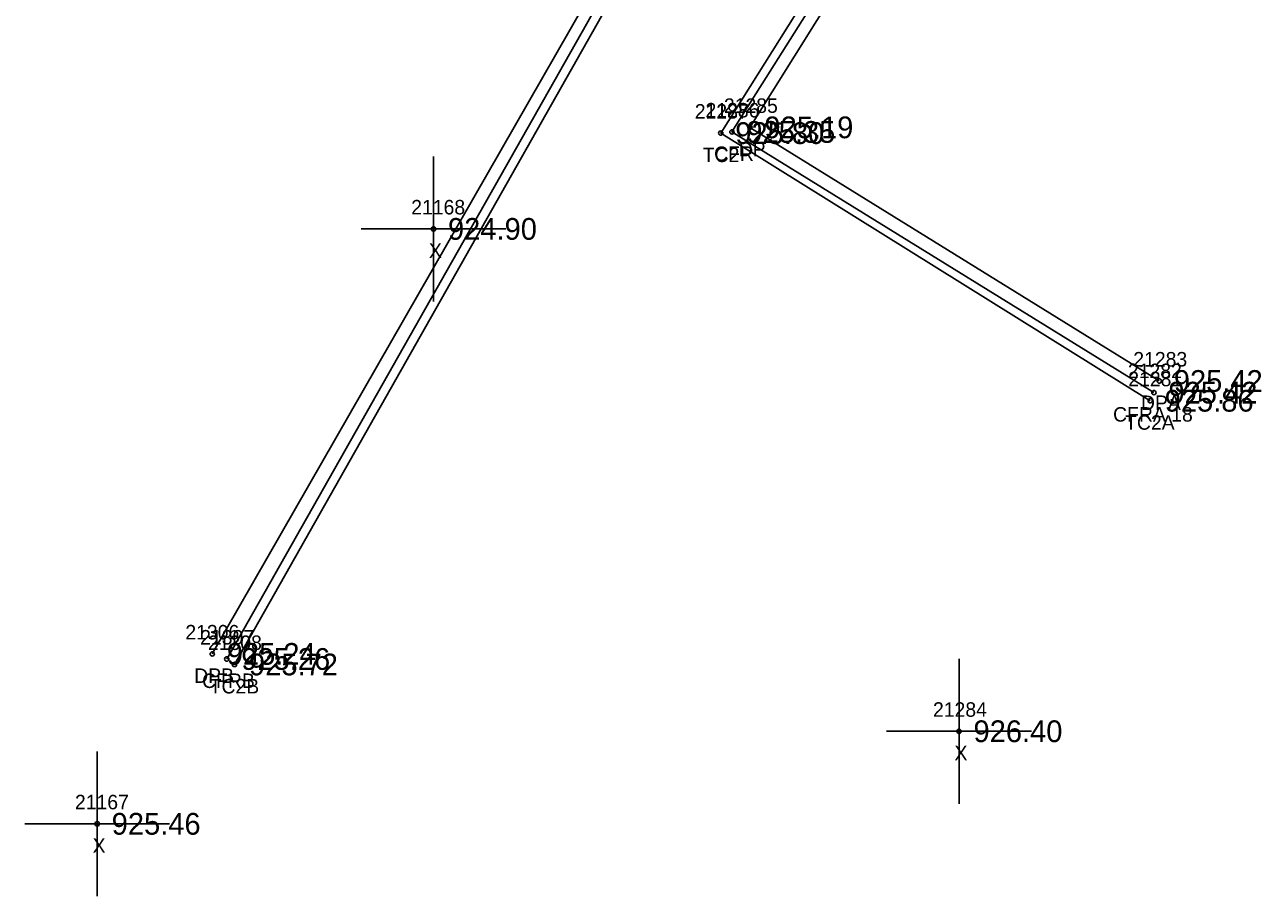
# Model space of a CAD drawing. Extents: x 1576181 to 1577685, y 1099396 to 1101490.
# Drawn here: x 1576872.8 to 1576958.1, y 1100219.7 to 1100279.9 of the extents above; entities that cross this region are included whole.
import ezdxf

# ---------------------------------------------------------------- set-up
doc = ezdxf.new("R2010")
doc.units = 0
for name, color, linetype in [('RD_DTM_BkLn2', 7, 'Continuous'), ('RD_EX_Conc', 7, 'Continuous'), ('RD_EX_Conc_txCode', 7, 'Continuous'), ('RD_EX_Driveway', 7, 'Continuous'), ('RD_EX_Driveway_txCode', 7, 'Continuous'), ('RD_EX_Misc', 7, 'Continuous'), ('RD_EX_Misc_txCode', 7, 'Continuous'), ('RD_EX_TX_Conc_ELEV', 7, 'Continuous'), ('RD_EX_TX_Driveway_ELEV', 7, 'Continuous'), ('RD_EX_TX_Misc_ELEV', 7, 'Continuous'), ('RD_SMD_Locator', 7, 'Continuous')]:
    doc.layers.add(name, color=color, linetype=linetype)

msp = doc.modelspace()

# ---------------------------------------------------------------- linework, layer by layer
at = {"layer": 'RD_DTM_BkLn2'}
msp.add_lwpolyline([(1576950.428, 1100253.929), (1576920.799, 1100272.396), (1576929.017, 1100285.487), (1576929.003, 1100287.192), (1576927.528, 1100288.17), (1576922.503, 1100288.122), (1576917.041, 1100286.162), (1576913.654, 1100282.404), (1576887.247, 1100235.73)], dxfattribs=at)
at = {"layer": 'RD_EX_Conc'}
msp.add_lwpolyline([(1576950.686, 1100254.487), (1576921.564, 1100272.475), (1576929.602, 1100285.245), (1576929.528, 1100287.387), (1576927.709, 1100288.698), (1576922.308, 1100288.785), (1576916.503, 1100286.517), (1576913.006, 1100282.543), (1576886.711, 1100236.108)], dxfattribs=at)
at = {"layer": 'RD_EX_Driveway'}
msp.add_lwpolyline([(1576951.058, 1100255.291), (1576922.81, 1100272.792), (1576930.511, 1100285.101), (1576930.352, 1100287.763), (1576927.798, 1100289.531), (1576922.044, 1100289.43), (1576915.936, 1100287.07), (1576912.303, 1100282.866), (1576885.713, 1100236.458)], dxfattribs=at)
at = {"layer": 'RD_EX_Misc'}
for p, q in [((1576900.976, 1100260.786), (1576900.976, 1100270.786)), ((1576895.976, 1100265.786), (1576905.976, 1100265.786)), ((1576937.237, 1100226.122), (1576937.237, 1100236.122)), ((1576932.237, 1100231.122), (1576942.237, 1100231.122)), ((1576877.771, 1100219.736), (1576877.771, 1100229.736)), ((1576872.771, 1100224.736), (1576882.771, 1100224.736))]:
    msp.add_line(p, q, dxfattribs=at)
at = {"layer": 'RD_SMD_Locator'}
for centre in [(1576922.81, 1100272.792), (1576920.799, 1100272.396), (1576921.564, 1100272.475), (1576900.976, 1100265.786), (1576951.058, 1100255.291), (1576950.428, 1100253.929), (1576950.686, 1100254.487), (1576885.713, 1100236.458), (1576886.711, 1100236.108), (1576887.247, 1100235.73), (1576937.237, 1100231.122), (1576877.771, 1100224.736)]:
    msp.add_circle(centre, 0.15, dxfattribs=at)

# ---------------------------------------------------------------- texts
at = {"layer": 'RD_EX_Conc_txCode'}
for s, p in [('21287', (1576919.004, 1100273.396)), ('21286', (1576919.745, 1100273.475)), ('TC2', (1576919.555, 1100270.396)), ('CFR', (1576920.335, 1100270.475)), ('21282', (1576948.891, 1100255.487)), ('21281', (1576948.916, 1100254.929)), ('CFRA 18', (1576947.867, 1100252.487)), ('TC2A', (1576948.696, 1100251.929)), ('21307', (1576884.877, 1100237.108)), ('21308', (1576885.413, 1100236.73)), ('CFRB', (1576885.01, 1100234.108)), ('TC2B', (1576885.531, 1100233.73))]:
    msp.add_text(s, height=1, dxfattribs=at).set_placement(p)
at = {"layer": 'RD_EX_Driveway_txCode'}
for s, p in [('21285', (1576921.015, 1100273.792)), ('DP', (1576922.03, 1100270.792)), ('21283', (1576949.262, 1100256.291)), ('DPA', (1576949.79, 1100253.291)), ('21306', (1576883.855, 1100237.458)), ('DPB', (1576884.461, 1100234.458))]:
    msp.add_text(s, height=1, dxfattribs=at).set_placement(p)
at = {"layer": 'RD_EX_Misc_txCode'}
for s, p in [('21168', (1576899.44, 1100266.786)), ('X', (1576900.661, 1100263.786)), ('21284', (1576935.442, 1100232.122)), ('X', (1576936.922, 1100229.122)), ('21167', (1576876.236, 1100225.736)), ('X', (1576877.456, 1100222.736))]:
    msp.add_text(s, height=1, dxfattribs=at).set_placement(p)
at = {"layer": 'RD_EX_TX_Conc_ELEV'}
for s, p in [('925.80', (1576921.799, 1100271.646)), ('925.35', (1576922.564, 1100271.725)), ('925.42', (1576951.686, 1100253.737)), ('925.86', (1576951.428, 1100253.179)), ('925.26', (1576887.711, 1100235.358)), ('925.72', (1576888.247, 1100234.98))]:
    msp.add_text(s, height=1.5, dxfattribs=at).set_placement(p)
at = {"layer": 'RD_EX_TX_Driveway_ELEV'}
for s, p in [('925.19', (1576923.81, 1100272.042)), ('925.42', (1576952.058, 1100254.541)), ('925.24', (1576886.713, 1100235.708))]:
    msp.add_text(s, height=1.5, dxfattribs=at).set_placement(p)
at = {"layer": 'RD_EX_TX_Misc_ELEV'}
for s, p in [('924.90', (1576901.976, 1100265.036)), ('926.40', (1576938.237, 1100230.372)), ('925.46', (1576878.771, 1100223.986))]:
    msp.add_text(s, height=1.5, dxfattribs=at).set_placement(p)

doc.saveas('drawing.dxf')
